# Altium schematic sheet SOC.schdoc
size 420 x 297 mm; Symbol: Drawing-Symbol_A4; Company: 嘉立创EDA; Version: V1.0; Page Size: A4; @Project Name: A113 Android MircroPhone; @Page Count: 5; @Update Date: 2025-09-30; @Create Date: 2025-08-09; @Schematic Name: Schematic1; @Page No: 4; @Page Name: SOC; @Create Time: 14:22:45; @Update Time: 20:53:25; Border: 1; Width: 1655; Height: 1170; Region Start: 1; X Region Count: 6; Y Region Count: 4; Blade Width: 10; Title Block Position: 3; @Board Name: Board1; Device: Drawing-Symbol_A4
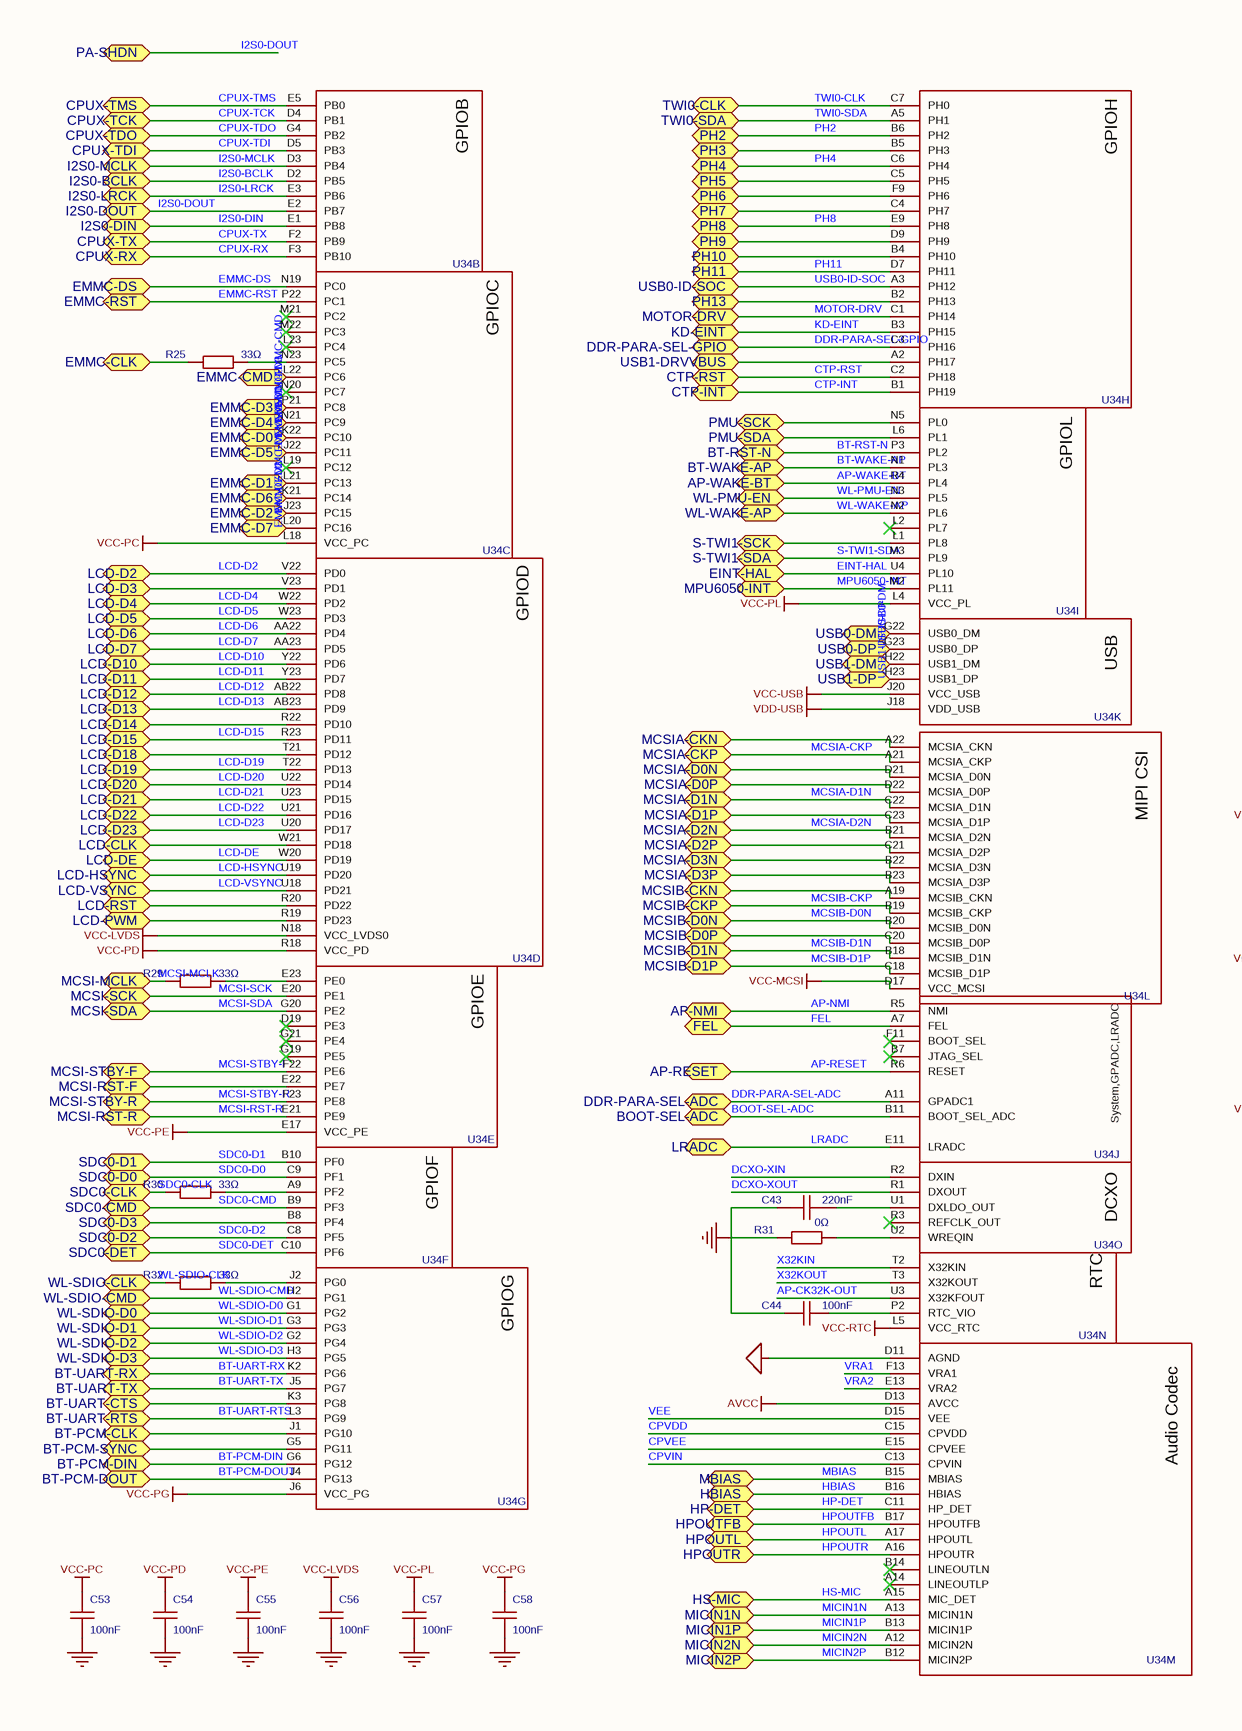
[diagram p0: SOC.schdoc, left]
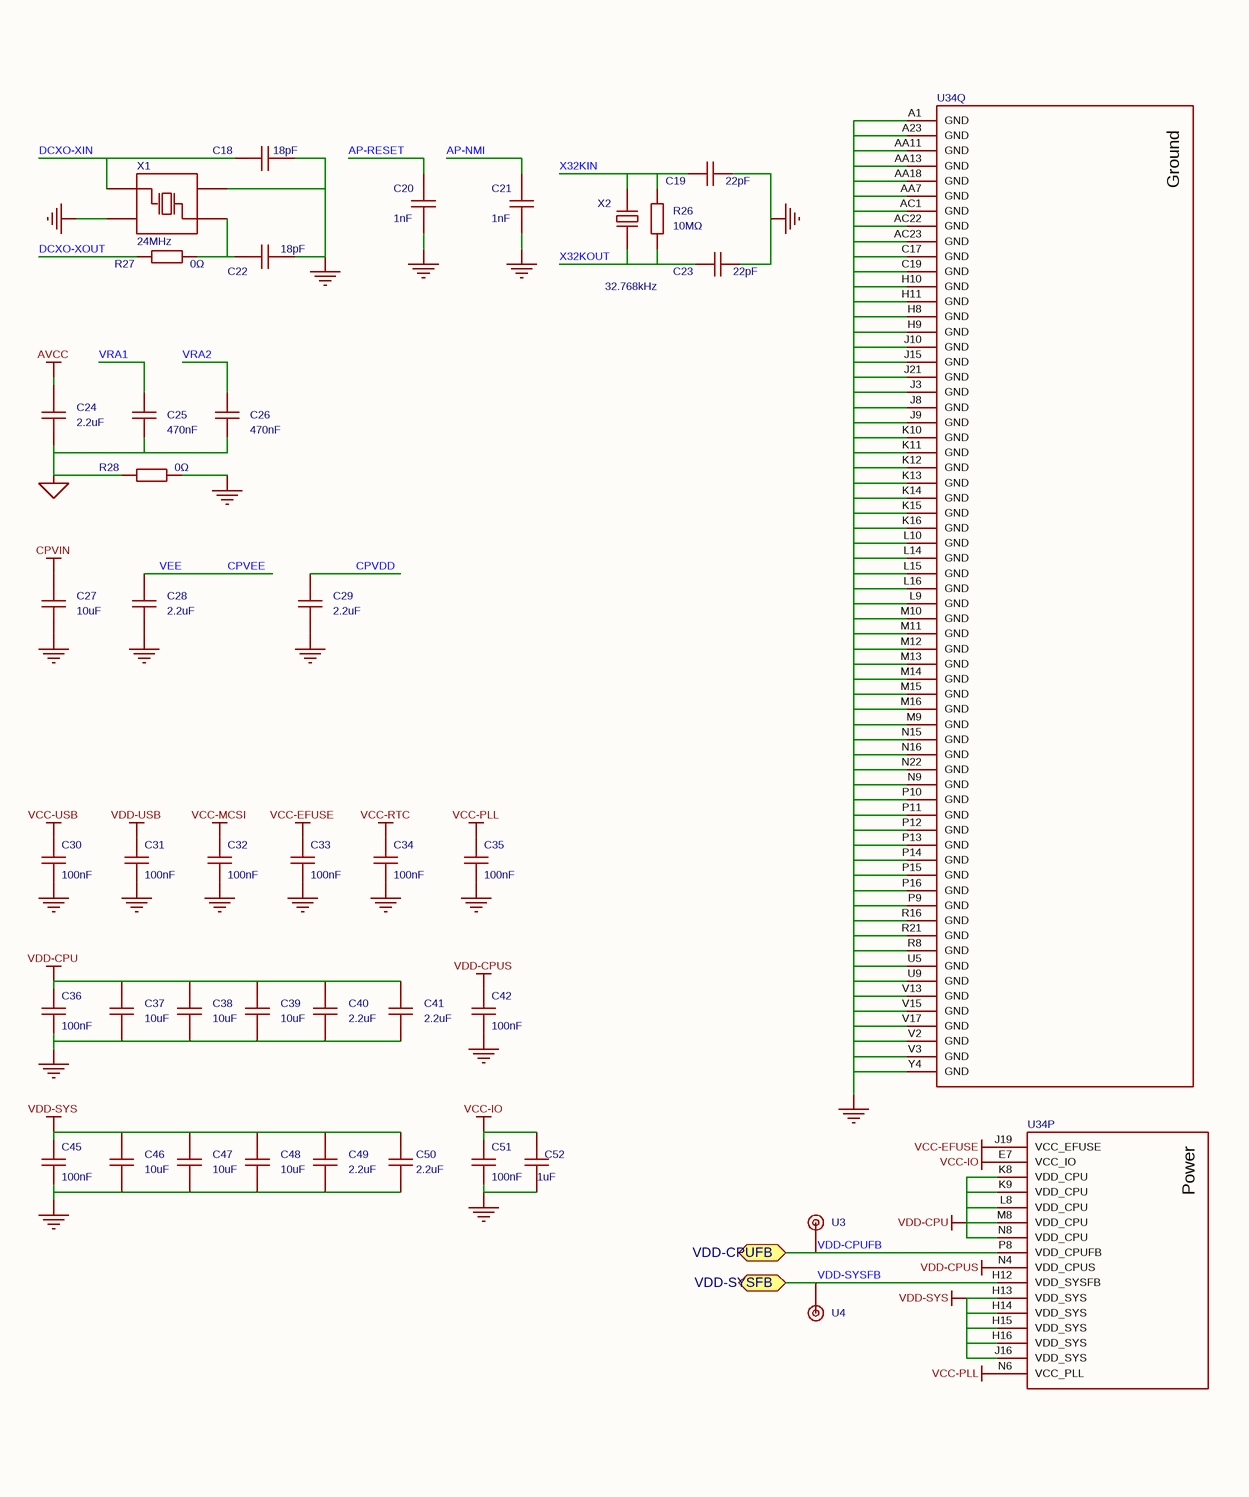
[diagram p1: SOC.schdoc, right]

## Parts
C18  18pF  [C0402]
C19  22pF  [C0402]
C20  1nF  [C0402]
C21  1nF  [C0402]
C22  18pF  [C0402]
C23  22pF  [C0402]
C24  2.2uF  [C0402]
C25  470nF  [C0402]
C26  470nF  [C0402]
C27  10uF  [C0603]
C28  2.2uF  [C0402]
C29  2.2uF  [C0402]
C30  100nF  [C0402]
C31  100nF  [C0402]
C32  100nF  [C0402]
C33  100nF  [C0402]
C34  100nF  [C0402]
C35  100nF  [C0402]
C36  100nF  [C0402]
C37  10uF  [C0603]
C38  10uF  [C0603]
C39  10uF  [C0603]
C40  2.2uF  [C0402]
C41  2.2uF  [C0402]
C42  100nF  [C0402]
C43  220nF  [C0402]
C44  100nF  [C0402]
C45  100nF  [C0402]
C46  10uF  [C0603]
C47  10uF  [C0603]
C48  10uF  [C0603]
C49  2.2uF  [C0402]
C50  2.2uF  [C0402]
C51  100nF  [C0402]
C52  1uF  [C0402]
C53  100nF  [C0402]
C54  100nF  [C0402]
C55  100nF  [C0402]
C56  100nF  [C0402]
C57  100nF  [C0402]
C58  100nF  [C0402]
R25  33Ω  [R0402]
R26  10MΩ  [R0402]
R27  0Ω  [R0402]
R28  0Ω  [R0402]
R29  33Ω  [R0402]
R30  33Ω  [R0402]
R31  0Ω  [R0402]
R32  33Ω  [R0402]
U3  测试焊盘  [焊盘]  (value not drawn)
U4  测试焊盘  [焊盘]  (value not drawn)
U34  A133  [LFBGA-346_L12.0-W12.0-P0.50-TL_ALLWINNER_A133]  (value not drawn)  (parts B,C,D,E,F,G,H,I,J,K,L,M,N,O,P,Q of 17)
X1  24MHz  [CRYSTAL-SMD_4P-L3.2-W2.5-BL]
X2  32.768kHz  [OSC-SMD_L3.2-W1.5]

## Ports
AP-NMI (bidir), AP-RESET (bidir), AP-WAKE-BT (bidir), BOOT-SEL-ADC (bidir), BT-PCM-CLK (bidir), BT-PCM-DIN (bidir), BT-PCM-DOUT (bidir), BT-PCM-SYNC (bidir), BT-RST-N (bidir), BT-UART-CTS (bidir), BT-UART-RTS (bidir), BT-UART-RX (bidir), BT-UART-TX (bidir), BT-WAKE-AP (bidir), CPUX-RX (bidir), CPUX-TCK (bidir), CPUX-TDI (bidir), CPUX-TDO (bidir), CPUX-TMS (bidir), CPUX-TX (bidir), CTP-INT (bidir), CTP-RST (bidir), DDR-PARA-SEL-ADC (bidir), DDR-PARA-SEL-GPIO (bidir), EINT-HAL (bidir), EMMC-CLK (bidir), EMMC-CMD (bidir), EMMC-D0 (bidir), EMMC-D1 (bidir), EMMC-D2 (bidir), EMMC-D3 (bidir), EMMC-D4 (bidir), EMMC-D5 (bidir), EMMC-D6 (bidir), EMMC-D7 (bidir), EMMC-DS (bidir), EMMC-RST (bidir), FEL (bidir), HBIAS (bidir), HP-DET (bidir), HPOUTFB (bidir), HPOUTL (bidir), HPOUTR (bidir), HS-MIC (bidir), I2S0-BCLK (bidir), I2S0-DIN (bidir), I2S0-DOUT (bidir), I2S0-LRCK (bidir), I2S0-MCLK (bidir), KD-EINT (bidir), LCD-CLK (bidir), LCD-D2 (bidir), LCD-D3 (bidir), LCD-D4 (bidir), LCD-D5 (bidir), LCD-D6 (bidir), LCD-D7 (bidir), LCD-D10 (bidir), LCD-D11 (bidir), LCD-D12 (bidir), LCD-D13 (bidir), LCD-D14 (bidir), LCD-D15 (bidir), LCD-D18 (bidir), LCD-D19 (bidir), LCD-D20 (bidir), LCD-D21 (bidir), LCD-D22 (bidir), LCD-D23 (bidir), LCD-DE (bidir), LCD-HSYNC (bidir), LCD-PWM (bidir), LCD-RST (bidir), LCD-VSYNC (bidir), LRADC (bidir), MBIAS (bidir), MCSI-MCLK (bidir), MCSI-RST-F (bidir), MCSI-RST-R (bidir), MCSI-SCK (bidir), MCSI-SDA (bidir), MCSI-STBY-F (bidir), MCSI-STBY-R (bidir), MCSIA-CKN (bidir), MCSIA-CKP (bidir), MCSIA-D0N (bidir), MCSIA-D0P (bidir), MCSIA-D1N (bidir), MCSIA-D1P (bidir), MCSIA-D2N (bidir), MCSIA-D2P (bidir), MCSIA-D3N (bidir), MCSIA-D3P (bidir), MCSIB-CKN (bidir), MCSIB-CKP (bidir), MCSIB-D0N (bidir), MCSIB-D0P (bidir), MCSIB-D1N (bidir), MCSIB-D1P (bidir), MICIN1N (bidir), MICIN1P (bidir), MICIN2N (bidir), MICIN2P (bidir), MOTOR-DRV (bidir), MPU6050-INT (bidir), PA-SHDN (bidir), PH2 (bidir), PH3 (bidir), PH4 (bidir), PH5 (bidir), PH6 (bidir), PH7 (bidir), PH8 (bidir), PH9 (bidir), PH10 (bidir), PH11 (bidir), PH13 (bidir), PMU-SCK (bidir), PMU-SDA (bidir), S-TWI1-SCK (bidir), S-TWI1-SDA (bidir), SDC0-CLK (bidir), SDC0-CMD (bidir), SDC0-D0 (bidir), SDC0-D1 (bidir), SDC0-D2 (bidir), SDC0-D3 (bidir), SDC0-DET (bidir), TWI0-CLK (bidir), TWI0-SDA (bidir), USB0-DM (bidir), USB0-DP (bidir), USB0-ID-SOC (bidir), USB1-DM (bidir), USB1-DP (bidir), USB1-DRVVBUS (bidir), VDD-CPUFB (bidir), VDD-SYSFB (bidir), WL-PMU-EN (bidir), WL-SDIO-CLK (bidir), WL-SDIO-CMD (bidir), WL-SDIO-D0 (bidir), WL-SDIO-D1 (bidir), WL-SDIO-D2 (bidir), WL-SDIO-D3 (bidir), WL-WAKE-AP (bidir)

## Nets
AGND: C24.1 C25.1 C26.1 R28.1 U34.D11(AGND)
AVCC: C24.2 U34.D13(AVCC)
CPVIN: C27.2 U34.C13(CPVIN)
GND: C18.1 C19.2 C20.1 C21.1 C22.1 C23.2 C27.1 C28.1 C29.1 C30.2 C31.2 C32.2 C33.2 C34.2 C35.2 C36.2 C37.1 C38.1 C39.1 C40.1 C41.1 C42.2 C43.2 C44.1 C45.2 C46.1 C47.1 C48.1 C49.1 C50.1 C51.2 C52.1 C53.2 C54.2 C55.2 C56.2 C57.2 C58.2 R28.2 R31.1 U34.A1(GND) U34.A23(GND) U34.AA7(GND) U34.AA11(GND) U34.AA13(GND) U34.AA18(GND) U34.AC1(GND) U34.AC22(GND) U34.AC23(GND) U34.C17(GND) U34.C19(GND) U34.H8(GND) U34.H9(GND) U34.H10(GND) U34.H11(GND) U34.J3(GND) U34.J8(GND) U34.J9(GND) U34.J10(GND) U34.J15(GND) U34.J21(GND) U34.K10(GND) U34.K11(GND) U34.K12(GND) U34.K13(GND) U34.K14(GND) U34.K15(GND) U34.K16(GND) U34.L9(GND) U34.L10(GND) U34.L14(GND) U34.L15(GND) U34.L16(GND) U34.M9(GND) U34.M10(GND) U34.M11(GND) U34.M12(GND) U34.M13(GND) U34.M14(GND) U34.M15(GND) U34.M16(GND) U34.N9(GND) U34.N15(GND) U34.N16(GND) U34.N22(GND) U34.P9(GND) U34.P10(GND) U34.P11(GND) U34.P12(GND) U34.P13(GND) U34.P14(GND) U34.P15(GND) U34.P16(GND) U34.R8(GND) U34.R16(GND) U34.R21(GND) U34.U5(GND) U34.U9(GND) U34.V2(GND) U34.V3(GND) U34.V13(GND) U34.V15(GND) U34.V17(GND) U34.Y4(GND) X1.2(GND) X1.4(GND)
VCC-EFUSE: C33.1 U34.J19(VCC_EFUSE)
VCC-IO: C51.1 C52.2 U34.E7(VCC_IO)
VCC-LVDS: C56.1 U34.N18(VCC_LVDS0)
VCC-MCSI: C32.1 U34.D17(VCC_MCSI)
VCC-PC: C53.1 U34.L18(VCC_PC)
VCC-PD: C54.1 U34.R18(VCC_PD)
VCC-PE: C55.1 U34.E17(VCC_PE)
VCC-PG: C58.1 U34.J6(VCC_PG)
VCC-PL: C57.1 U34.L4(VCC_PL)
VCC-PLL: C35.1 U34.N6(VCC_PLL)
VCC-RTC: C34.1 U34.L5(VCC_RTC)
VCC-USB: C30.1 U34.J20(VCC_USB)
VDD-CPU: C36.1 C37.2 C38.2 C39.2 C40.2 C41.2 U34.K8(VDD_CPU) U34.K9(VDD_CPU) U34.L8(VDD_CPU) U34.M8(VDD_CPU) U34.N8(VDD_CPU)
VDD-CPUS: C42.1 U34.N4(VDD_CPUS)
VDD-SYS: C45.1 C46.2 C47.2 C48.2 C49.2 C50.2 U34.H13(VDD_SYS) U34.H14(VDD_SYS) U34.H15(VDD_SYS) U34.H16(VDD_SYS) U34.J16(VDD_SYS)
VDD-USB: C31.1 U34.J18(VDD_USB)
AP-CK32K-OUT: U34.U3(X32KFOUT)
AP-NMI: C21.2 U34.R5(NMI) ; port AP-NMI
AP-RESET: C20.2 U34.R6(RESET) ; port AP-RESET
AP-WAKE-BT: U34.R4(PL4) ; port AP-WAKE-BT
BOOT-SEL-ADC: U34.B11(BOOT_SEL_ADC) ; port BOOT-SEL-ADC
BT-PCM-CLK: U34.J1(PG10) ; port BT-PCM-CLK
BT-PCM-DIN: U34.G6(PG12) ; port BT-PCM-DIN
BT-PCM-DOUT: U34.J4(PG13) ; port BT-PCM-DOUT
BT-PCM-SYNC: U34.G5(PG11) ; port BT-PCM-SYNC
BT-RST-N: U34.P3(PL2) ; port BT-RST-N
BT-UART-CTS: U34.K3(PG8) ; port BT-UART-CTS
BT-UART-RTS: U34.L3(PG9) ; port BT-UART-RTS
BT-UART-RX: U34.K2(PG6) ; port BT-UART-RX
BT-UART-TX: U34.J5(PG7) ; port BT-UART-TX
BT-WAKE-AP: U34.N1(PL3) ; port BT-WAKE-AP
CPUX-RX: U34.F3(PB10) ; port CPUX-RX
CPUX-TCK: U34.D4(PB1) ; port CPUX-TCK
CPUX-TDI: U34.D5(PB3) ; port CPUX-TDI
CPUX-TDO: U34.G4(PB2) ; port CPUX-TDO
CPUX-TMS: U34.E5(PB0) ; port CPUX-TMS
CPUX-TX: U34.F2(PB9) ; port CPUX-TX
CPVDD: C29.2 U34.C15(CPVDD)
CPVEE: C28.2 U34.D15(VEE) U34.E15(CPVEE)  [also labelled VEE]
CTP-INT: U34.B1(PH19) ; port CTP-INT
CTP-RST: U34.C2(PH18) ; port CTP-RST
DCXO-XIN: C18.2 U34.R2(DXIN) X1.1(OSC1)
DCXO-XOUT: R27.1 U34.R1(DXOUT)
DDR-PARA-SEL-ADC: U34.A11(GPADC1) ; port DDR-PARA-SEL-ADC
DDR-PARA-SEL-GPIO: U34.C3(PH16) ; port DDR-PARA-SEL-GPIO
EINT-HAL: U34.U4(PL10) ; port EINT-HAL
EMMC-CLK: R25.1 ; port EMMC-CLK
EMMC-CMD: U34.L22(PC6) ; port EMMC-CMD
EMMC-D0: U34.K22(PC10) ; port EMMC-D0
EMMC-D1: U34.L21(PC13) ; port EMMC-D1
EMMC-D2: U34.J23(PC15) ; port EMMC-D2
EMMC-D3: U34.P21(PC8) ; port EMMC-D3
EMMC-D4: U34.N21(PC9) ; port EMMC-D4
EMMC-D5: U34.J22(PC11) ; port EMMC-D5
EMMC-D6: U34.K21(PC14) ; port EMMC-D6
EMMC-D7: U34.L20(PC16) ; port EMMC-D7
EMMC-DS: U34.N19(PC0) ; port EMMC-DS
EMMC-RST: U34.P22(PC1) ; port EMMC-RST
FEL: U34.A7(FEL) ; port FEL
HBIAS: U34.B16(HBIAS) ; port HBIAS
HP-DET: U34.C11(HP_DET) ; port HP-DET
HPOUTFB: U34.B17(HPOUTFB) ; port HPOUTFB
HPOUTL: U34.A17(HPOUTL) ; port HPOUTL
HPOUTR: U34.A16(HPOUTR) ; port HPOUTR
HS-MIC: U34.A15(MIC_DET) ; port HS-MIC
I2S0-BCLK: U34.D2(PB5) ; port I2S0-BCLK
I2S0-DIN: U34.E1(PB8) ; port I2S0-DIN
I2S0-DOUT: U34.E2(PB7) ; port I2S0-DOUT, port PA-SHDN
I2S0-LRCK: U34.E3(PB6) ; port I2S0-LRCK
I2S0-MCLK: U34.D3(PB4) ; port I2S0-MCLK
KD-EINT: U34.B3(PH15) ; port KD-EINT
LCD-CLK: U34.W21(PD18) ; port LCD-CLK
LCD-D2: U34.V22(PD0) ; port LCD-D2
LCD-D3: U34.V23(PD1) ; port LCD-D3
LCD-D4: U34.W22(PD2) ; port LCD-D4
LCD-D5: U34.W23(PD3) ; port LCD-D5
LCD-D6: U34.AA22(PD4) ; port LCD-D6
LCD-D7: U34.AA23(PD5) ; port LCD-D7
LCD-D10: U34.Y22(PD6) ; port LCD-D10
LCD-D11: U34.Y23(PD7) ; port LCD-D11
LCD-D12: U34.AB22(PD8) ; port LCD-D12
LCD-D13: U34.AB23(PD9) ; port LCD-D13
LCD-D14: U34.R22(PD10) ; port LCD-D14
LCD-D15: U34.R23(PD11) ; port LCD-D15
LCD-D18: U34.T21(PD12) ; port LCD-D18
LCD-D19: U34.T22(PD13) ; port LCD-D19
LCD-D20: U34.U22(PD14) ; port LCD-D20
LCD-D21: U34.U23(PD15) ; port LCD-D21
LCD-D22: U34.U21(PD16) ; port LCD-D22
LCD-D23: U34.U20(PD17) ; port LCD-D23
LCD-DE: U34.W20(PD19) ; port LCD-DE
LCD-HSYNC: U34.U19(PD20) ; port LCD-HSYNC
LCD-PWM: U34.R19(PD23) ; port LCD-PWM
LCD-RST: U34.R20(PD22) ; port LCD-RST
LCD-VSYNC: U34.U18(PD21) ; port LCD-VSYNC
LRADC: U34.E11(LRADC) ; port LRADC
MBIAS: U34.B15(MBIAS) ; port MBIAS
MCSI-MCLK: R29.1 ; port MCSI-MCLK
MCSI-RST-F: U34.E22(PE7) ; port MCSI-RST-F
MCSI-RST-R: U34.E21(PE9) ; port MCSI-RST-R
MCSI-SCK: U34.E20(PE1) ; port MCSI-SCK
MCSI-SDA: U34.G20(PE2) ; port MCSI-SDA
MCSI-STBY-F: U34.F22(PE6) ; port MCSI-STBY-F
MCSI-STBY-R: U34.F23(PE8) ; port MCSI-STBY-R
MCSIA-CKN: U34.A22(MCSIA_CKN) ; port MCSIA-CKN
MCSIA-CKP: U34.A21(MCSIA_CKP) ; port MCSIA-CKP
MCSIA-D0N: U34.D21(MCSIA_D0N) ; port MCSIA-D0N
MCSIA-D0P: U34.D22(MCSIA_D0P) ; port MCSIA-D0P
MCSIA-D1N: U34.C22(MCSIA_D1N) ; port MCSIA-D1N
MCSIA-D1P: U34.C23(MCSIA_D1P) ; port MCSIA-D1P
MCSIA-D2N: U34.B21(MCSIA_D2N) ; port MCSIA-D2N
MCSIA-D2P: U34.C21(MCSIA_D2P) ; port MCSIA-D2P
MCSIA-D3N: U34.B22(MCSIA_D3N) ; port MCSIA-D3N
MCSIA-D3P: U34.B23(MCSIA_D3P) ; port MCSIA-D3P
MCSIB-CKN: U34.A19(MCSIB_CKN) ; port MCSIB-CKN
MCSIB-CKP: U34.B19(MCSIB_CKP) ; port MCSIB-CKP
MCSIB-D0N: U34.B20(MCSIB_D0N) ; port MCSIB-D0N
MCSIB-D0P: U34.C20(MCSIB_D0P) ; port MCSIB-D0P
MCSIB-D1N: U34.B18(MCSIB_D1N) ; port MCSIB-D1N
MCSIB-D1P: U34.C18(MCSIB_D1P) ; port MCSIB-D1P
MICIN1N: U34.A13(MICIN1N) ; port MICIN1N
MICIN1P: U34.B13(MICIN1P) ; port MICIN1P
MICIN2N: U34.A12(MICIN2N) ; port MICIN2N
MICIN2P: U34.B12(MICIN2P) ; port MICIN2P
MOTOR-DRV: U34.C1(PH14) ; port MOTOR-DRV
MPU6050-INT: U34.M2(PL11) ; port MPU6050-INT
PH2: U34.B6(PH2) ; port PH2
PH3: U34.B5(PH3) ; port PH3
PH4: U34.C6(PH4) ; port PH4
PH5: U34.C5(PH5) ; port PH5
PH6: U34.F9(PH6) ; port PH6
PH7: U34.C4(PH7) ; port PH7
PH8: U34.E9(PH8) ; port PH8
PH9: U34.D9(PH9) ; port PH9
PH10: U34.B4(PH10) ; port PH10
PH11: U34.D7(PH11) ; port PH11
PH13: U34.B2(PH13) ; port PH13
PMU-SCK: U34.N5(PL0) ; port PMU-SCK
PMU-SDA: U34.L6(PL1) ; port PMU-SDA
S-TWI1-SCK: U34.L1(PL8) ; port S-TWI1-SCK
S-TWI1-SDA: U34.M3(PL9) ; port S-TWI1-SDA
SDC0-CLK: R30.1 ; port SDC0-CLK
SDC0-CMD: U34.B9(PF3) ; port SDC0-CMD
SDC0-D0: U34.C9(PF1) ; port SDC0-D0
SDC0-D1: U34.B10(PF0) ; port SDC0-D1
SDC0-D2: U34.C8(PF5) ; port SDC0-D2
SDC0-D3: U34.B8(PF4) ; port SDC0-D3
SDC0-DET: U34.C10(PF6) ; port SDC0-DET
TWI0-CLK: U34.C7(PH0) ; port TWI0-CLK
TWI0-SDA: U34.A5(PH1) ; port TWI0-SDA
USB0-DM: U34.G22(USB0_DM) ; port USB0-DM
USB0-DP: U34.G23(USB0_DP) ; port USB0-DP
USB0-ID-SOC: U34.A3(PH12) ; port USB0-ID-SOC
USB1-DM: U34.H22(USB1_DM) ; port USB1-DM
USB1-DP: U34.H23(USB1_DP) ; port USB1-DP
USB1-DRVVBUS: U34.A2(PH17) ; port USB1-DRVVBUS
VDD-CPUFB: U3.1 U34.P8(VDD_CPUFB) ; port VDD-CPUFB
VDD-SYSFB: U4.1 U34.H12(VDD_SYSFB) ; port VDD-SYSFB
VRA1: C25.2 U34.F13(VRA1)
VRA2: C26.2 U34.E13(VRA2)
WL-PMU-EN: U34.N3(PL5) ; port WL-PMU-EN
WL-SDIO-CLK: R32.1 ; port WL-SDIO-CLK
WL-SDIO-CMD: U34.H2(PG1) ; port WL-SDIO-CMD
WL-SDIO-D0: U34.G1(PG2) ; port WL-SDIO-D0
WL-SDIO-D1: U34.G3(PG3) ; port WL-SDIO-D1
WL-SDIO-D2: U34.G2(PG4) ; port WL-SDIO-D2
WL-SDIO-D3: U34.H3(PG5) ; port WL-SDIO-D3
WL-WAKE-AP: U34.N2(PL6) ; port WL-WAKE-AP
X32KIN: C19.1 R26.2 U34.T2(X32KIN) X2.2
X32KOUT: C23.1 R26.1 U34.T3(X32KOUT) X2.1
NetC22_2: C22.2 R27.2 X1.3(OSC2)
NetC43_1: C43.1 U34.U1(DXLDO_OUT)
NetC44_2: C44.2 U34.P2(RTC_VIO)
NetR25_2: R25.2 U34.N23(PC5)
NetR29_2: R29.2 U34.E23(PE0)
NetR30_2: R30.2 U34.A9(PF2)
NetR31_2: R31.2 U34.U2(WREQIN)
NetR32_2: R32.2 U34.J2(PG0)

Not connected (* = marked no-connect by the designer): U34 A14(LINEOUTLP)* B7(JTAG_SEL)* B14(LINEOUTLN)* D19(PE3)* F11(BOOT_SEL)* G19(PE5)* G21(PE4)* L2(PL7)* L19(PC12)* L23(PC4)* M21(PC2)* M22(PC3)* N20(PC7)* R3(REFCLK_OUT)*

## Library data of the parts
C18 C22 = CL05C180JB5NNNC: 容值:18pF;精度:±5%;额定电压:50V;材质(温度系数):C0G;; Manufacturer: SAMSUNG(三星); AddInBom: yes; ModelId: 36a51122f27c49738f86b3bfa98863e0; ModelName: C0402_L1.0-W0.5-H0.5; ModelTransform: 39.37,19.685,0,0,0,0,0,0,0; Tolerance: ±5%; Voltage Rated: 50V; Temperature Coefficient: C0G
C19 C23 = CL05C220JB5NNNC: 容值:22pF;精度:±5%;额定电压:50V;材质(温度系数):C0G;; Manufacturer: SAMSUNG(三星); Symbol: CL10C220JB8NNNC; AddInBom: yes; ModelId: 36a51122f27c49738f86b3bfa98863e0; ModelName: C0402_L1.0-W0.5-H0.5; ModelTransform: 39.37,19.685,0,0,0,0,0,0,0; Tolerance: ±5%; Voltage Rated: 50V; Temperature Coefficient: C0G
C20 C21 = CL05C102JB5NNNC: 容值:1nF;精度:±5%;额定电压:50V;材质(温度系数):C0G;; Manufacturer: SAMSUNG(三星); AddInBom: yes; ModelId: 36a51122f27c49738f86b3bfa98863e0; ModelName: C0402_L1.0-W0.5-H0.5; ModelTransform: 39.37,19.685,0,0,0,0,0,0,0; Tolerance: ±5%; Voltage Rated: 50V; Temperature Coefficient: C0G
C24 C28 C29 C40 C41 C49 C50 = CL05A225KP5NSNC: 容值:2.2uF;精度:±10%;额定电压:10V;材质(温度系数):X5R;; Manufacturer: SAMSUNG(三星); AddInBom: yes; ModelId: 36a51122f27c49738f86b3bfa98863e0; ModelName: C0402_L1.0-W0.5-H0.5; ModelTransform: 39.37,19.685,0,0,0,0,0,0,0; Tolerance: ±10%; Voltage Rated: 10V; Temperature Coefficient: X5R
C25 C26 = CL05A474KP5NNNC: 容值:470nF;精度:±10%;额定电压:10V;材质(温度系数):X5R;; Manufacturer: SAMSUNG(三星); AddInBom: yes; ModelId: 36a51122f27c49738f86b3bfa98863e0; ModelName: C0402_L1.0-W0.5-H0.5; ModelTransform: 39.37,19.685,0,0,0,0,0,0,0; Tolerance: ±10%; Voltage Rated: 10V; Temperature Coefficient: X5R
C27 C37-C39 C46-C48 = CL10A106KP8NNNC: 容值:10uF;精度:±10%;额定电压:10V;材质(温度系数):X5R;; Manufacturer: SAMSUNG(三星); AddInBom: yes; ModelId: ac125912035d415993ca9572d50418b1; ModelName: C0603_L1.6-W0.8-H0.8; ModelTransform: 62.992,31.496,0,0,0,0,0,0,0; Tolerance: ±10%; Voltage Rated: 10V; Temperature Coefficient: X5R
C30-C36 C42 C44 C45 C51 C53-C58 = CL05B104KO5NNNC: 容值:100nF;精度:±10%;额定电压:16V;材质(温度系数):X7R;; Manufacturer: SAMSUNG(三星); AddInBom: yes; ModelId: 36a51122f27c49738f86b3bfa98863e0; ModelName: C0402_L1.0-W0.5-H0.5; ModelTransform: 39.37,19.685,0,0,0,0,0,0,0; Tolerance: ±10%; Voltage Rated: 16V; Temperature Coefficient: X7R
C43 = CL05B224KP5NNNC: 容值:220nF;精度:±10%;额定电压:10V;材质(温度系数):X7R;; Manufacturer: SAMSUNG(三星); AddInBom: yes; ModelId: 36a51122f27c49738f86b3bfa98863e0; ModelName: C0402_L1.0-W0.5-H0.5; ModelTransform: 39.37,19.685,0,0,0,0,0,0,0; Tolerance: ±10%; Voltage Rated: 10V; Temperature Coefficient: X7R
C52 = CL05A105KA5NQNC: 容值:1uF;精度:±10%;额定电压:25V;材质(温度系数):X5R;; Manufacturer: SAMSUNG(三星); AddInBom: yes; ModelId: 36a51122f27c49738f86b3bfa98863e0; ModelName: C0402_L1.0-W0.5-H0.5; ModelTransform: 39.37,19.685,0,0,0,0,0,0,0; Tolerance: ±10%; Voltage Rated: 25V; Temperature Coefficient: X5R
R25 R29 R30 R32 = RC0402FR-0733RL: 电阻类型:厚膜电阻;阻值:33Ω;精度:±1%;功率:62.5mW;; Manufacturer: YAGEO(国巨); AddInBom: yes; ModelId: 671aefced39d4c318694bba8bd8efd39; ModelName: R0402_L1.0-W0.5-H0.5; ModelTransform: 39.37,19.685,0,0,0,0,0,0.0005,0; Tolerance: ±1%; Power(Watts): 62.5mW; Temperature Coefficient: ±100ppm/℃; Overload Voltage (Max): 50V
R26 = RC0402FR-0710ML: 电阻类型:厚膜电阻;阻值:10MΩ;精度:±1%;功率:62.5mW;; Manufacturer: YAGEO(国巨); AddInBom: yes; ModelId: 671aefced39d4c318694bba8bd8efd39; ModelName: R0402_L1.0-W0.5-H0.5; ModelTransform: 39.37,19.685,0,0,0,0,0,0.0005,0; Tolerance: ±1%; Power(Watts): 62.5mW; Temperature Coefficient: ±100ppm/℃; Overload Voltage (Max): 50V
R27 R28 R31 = RC0402JR-070RL: 电阻类型:厚膜电阻;阻值:0Ω;精度:-;功率:62.5mW;; Manufacturer: YAGEO(国巨); AddInBom: yes; ModelId: 671aefced39d4c318694bba8bd8efd39; ModelName: R0402_L1.0-W0.5-H0.5; ModelTransform: 39.37,19.685,0,0,0,0,0,0.0005,0; Power(Watts): 62.5mW; Overload Voltage (Max): 50V
U3 U4 = 测试焊盘: Add into BOM: no; ConvertToPcb: yes; _: 3
U34 = A133: CPU内核:-;CPU最大主频:-;程序存储容量:-;程序存储器类型:-;RAM总容量:-;GPIO端口数量:-;; Manufacturer: Allwinner(全志); AddInBom: yes; ModelId: fdc1d13f198041f4a5f47084645a4f81; ModelTransform: 472.44,472.44,0,0,0,0,0,0,0
X1 = X322524MPB4SI: 频率:24MHz;频率公差:±10ppm;负载电容:15pF;; Manufacturer: YXC(扬兴晶振); AddInBom: yes; ModelId: 1840cb1b89674ca18acb69eedbab271b; ModelName: OSC-SMD_4P-L3.2-W2.5-H1.0; ModelTransform: 125.984,98.425,0,0,0,0,0,0,0; Crystal Type: 贴片无源晶振; Frequency Tolerance: ±10ppm; Frequency Stability: ±30ppm; Load Capacitance: 15pF
X2 = X321532768KGD2SI: 频率:32.768kHz;频率公差:±20ppm;负载电容:12.5pF;; Manufacturer: YXC(扬兴晶振); AddInBom: yes; ModelId: 2dd241c0893b4675b8def6f6998a8251; ModelName: OSC-SMD_L3.2-W1.5-H0.8; ModelTransform: 125.984,59.055,0,0,0,0,0,-0.0005,0; Crystal Type: 贴片无源晶振; Frequency Tolerance: ±20ppm; Load Capacitance: 12.5pF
